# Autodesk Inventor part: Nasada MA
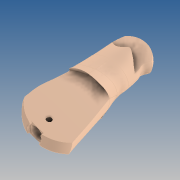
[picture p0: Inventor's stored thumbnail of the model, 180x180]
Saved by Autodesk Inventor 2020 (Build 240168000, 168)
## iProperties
Created: 2019-10
Part Number: Nasada MA
Material: GFRP
Document SubType Name: Modeling
Designer: yello
Density: 1.75 g/cm^3
Appearance: Default
Author: yello
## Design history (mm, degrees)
feature "Nasada MA"
workplane "Work Plane1"
sketch "Sketch2"
  geometry: L1 (3.5, 0)-(3.5, 20); L2 (3.5, 20)-(-3.5, 20); L3 (-3.5, 20)-(-3.5, 0); L4 (-3.5, 0)-(-3.5, -30); L5 (-3.5, -30)-(3.5, -30); L6 (3.5, -30)-(3.5, 0); L7 (0, -30)-(0, 20); A1 r 3.5 centre (0, 0) between (3.5, 0) and (-3.5, 0)
  constraints: 14 end point, 3 perpendicular, 2 midpoint, 2 point on circle, 2 point on line, 2 tangent, 1 centre point, 1 vertical
  dimensions: "d1" = 7 diameter of A1; "d2" = 20 distance of L1.start L1.end; "d3" = 30 distance of L3.end L4.end
revolve "Revolution1" sketch "Sketch2" stored, may be unused: angle "d4" = 90 deg
workplane "Work Plane2"
sketch "Sketch3"
  geometry: C1 r 4.25 at (0, 0)
  constraints: 1 centre point
  dimensions: "d6" = 8.5 diameter of C1
extrude "Extrusion1" cut sketch "Sketch3" distance "d7" = 1.75; taper "d8" = 0 deg
workplane "Work Plane3"
sketch "Sketch4" dims "d11" = 3
  geometry: L1 (-9.402, 20.348)-(-2.646, 18.513) reference; L2 (-6.024, 19.43)-(-13.888, -9.521); L3 (-13.888, -9.521)-(-14.281, -10.969); 2 further points
  constraints: 4 end point, 1 coincident, 1 midpoint, 3 other
  dimensions: "d10" = 30 distance of L2.start L2.end
revolve "Revolution2" sketch "Sketch4" stored, may be unused: angle "d12" = 90 deg
mirror "Mirror2"
workplane "Work Plane4"
sketch "Sketch7"
  geometry: L1 (0, 0)-(0, 7) reference; L2 (0, 3.5)-(3.75, 3.5); L3 (3.75, 3.5)-(7.75, 3.5); L4 (3.75, 2.5)-(7.75, 2.5); L5 (7.75, 4.5)-(3.75, 4.5); A1 r 1 centre (3.75, 3.5) between (3.75, 4.5) and (3.75, 2.5); A2 r 1 centre (7.75, 3.5) between (7.75, 2.5) and (7.75, 4.5); 1 further point
  constraints: 10 end point, 4 point on circle, 4 tangent, 2 centre point, 2 horizontal, 2 midpoint, 1 parallel
  dimensions: "d16" = 3.75 distance of L2.start L2.end; "d17" = 4 distance of L2.end L3.end; "d18" = 2 diameter of A2
extrude "Extrusion3" cut sketch "Sketch7" distance "d19" = 3453; taper "d20" = 0 deg
fillet "Fillet1" dims "d21" = 1
body "Solid1"
other parameters: "d5" = 38, "d9" = -0.5
